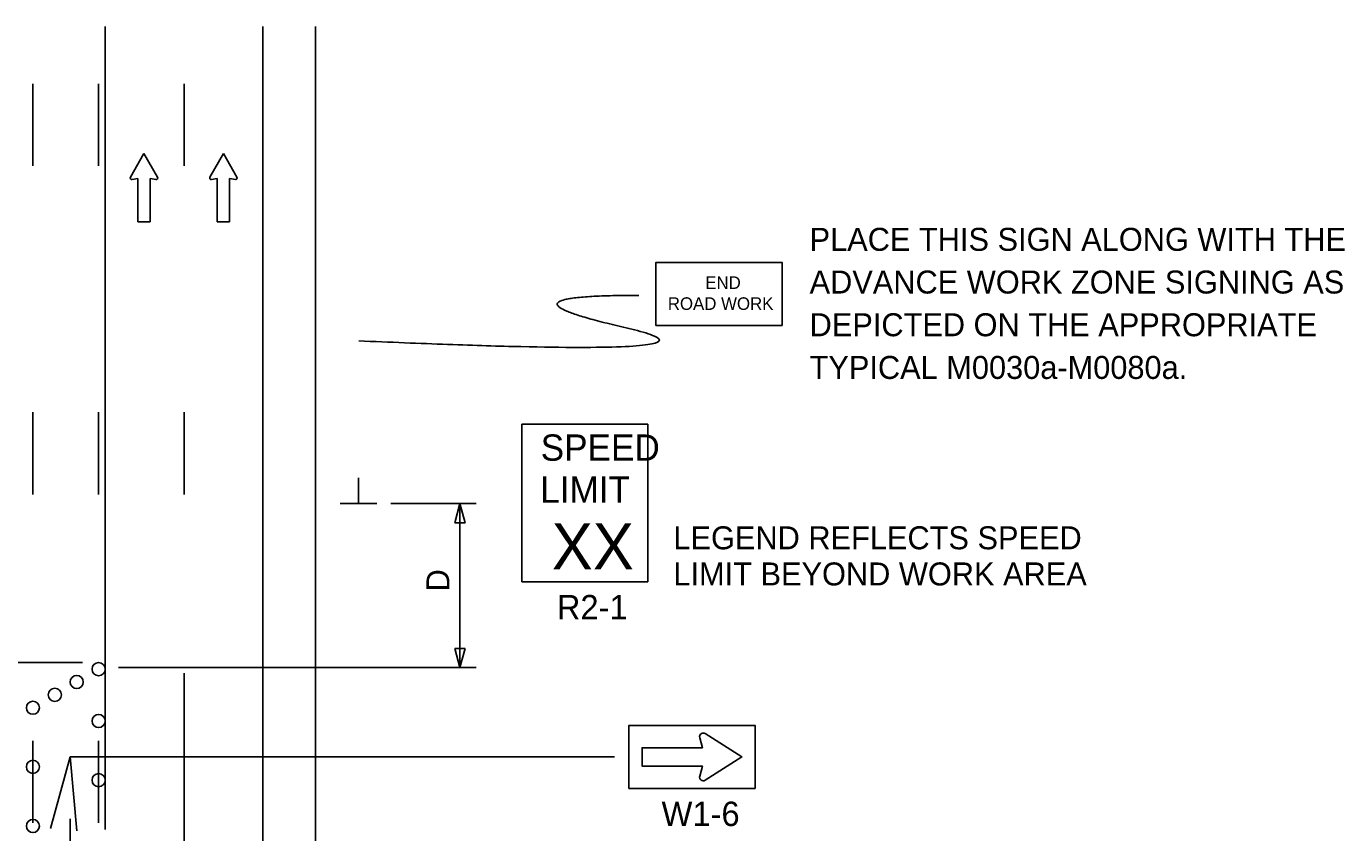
# Model space of a CAD drawing. Extents: x 16577 to 18475, y 5712 to 6919.
# Drawn here: x 16970.7 to 17372.2, y 6656 to 6901.4 of the extents above; entities that cross this region are included whole.
import ezdxf

# ---------------------------------------------------------------- set-up
doc = ezdxf.new("R2010")
doc.units = 0
for name, color, linetype in [('ALI_LEGAL_EX', 7, 'Continuous'), ('MT_SCRATCH_LEVEL_E', 7, 'Continuous'), ('PAVT_EDGE_EX', 7, 'Continuous'), ('TRAFFIC_SIGNS_PR', 7, 'Continuous'), ('TYPICAL_TEXT_DIMEN_PR', 7, 'Continuous')]:
    doc.layers.add(name, color=color, linetype=linetype)

msp = doc.modelspace()

# ---------------------------------------------------------------- linework, layer by layer
at = {"layer": 'ALI_LEGAL_EX'}
for points in [[(16972.75, 6883.94), (16972.75, 6858.94)], [(16992.75, 6883.94), (16992.75, 6858.94)], [(17018.75, 6883.94), (17018.75, 6858.94)], [(16972.75, 6783.94), (16972.75, 6758.94)], [(16992.75, 6783.94), (16992.75, 6758.94)], [(17018.75, 6783.94), (17018.75, 6758.94)], [(16972.75, 6683.94), (16972.75, 6658.94)], [(16992.75, 6683.94), (16992.75, 6658.94)], [(17018.75, 6683.94), (17018.75, 6659.28)]]:
    msp.add_lwpolyline(points, dxfattribs=at)
at = {"layer": 'MT_SCRATCH_LEVEL_E'}
for p, q in [((17006.56, 6862.73), (17002.45, 6855.49)), ((17006.56, 6862.73), (17002.45, 6855.49)), ((17010.71, 6855.49), (17006.56, 6862.73)), ((17010.71, 6855.49), (17006.56, 6862.73)), ((17030.73, 6862.73), (17026.62, 6855.49)), ((17030.73, 6862.73), (17026.62, 6855.49)), ((17034.88, 6855.49), (17030.73, 6862.73)), ((17034.88, 6855.49), (17030.73, 6862.73)), ((17002.93, 6854.81), (17004.71, 6855.12)), ((17002.93, 6854.81), (17004.71, 6855.12)), ((17004.71, 6855.12), (17004.71, 6841.87)), ((17004.71, 6855.12), (17004.71, 6841.87)), ((17008.45, 6841.87), (17008.45, 6855.12)), ((17008.45, 6855.12), (17010.23, 6854.81)), ((17008.45, 6841.87), (17008.45, 6855.12)), ((17008.45, 6855.12), (17010.23, 6854.81)), ((17027.1, 6854.81), (17028.88, 6855.12)), ((17027.1, 6854.81), (17028.88, 6855.12)), ((17028.88, 6855.12), (17028.88, 6841.87)), ((17028.88, 6855.12), (17028.88, 6841.87)), ((17032.62, 6841.87), (17032.62, 6855.12)), ((17032.62, 6855.12), (17034.4, 6854.81)), ((17032.62, 6841.87), (17032.62, 6855.12)), ((17032.62, 6855.12), (17034.4, 6854.81)), ((17004.71, 6841.87), (17008.45, 6841.87)), ((17004.71, 6841.87), (17008.45, 6841.87)), ((17028.88, 6841.87), (17032.62, 6841.87)), ((17028.88, 6841.87), (17032.62, 6841.87))]:
    msp.add_line(p, q, dxfattribs=at)
for centre, start, end in [((17002.86, 6855.27), 150.4248, 279.9638), ((17002.86, 6855.27), 150.4248, 279.9638), ((17010.3, 6855.27), 260.0362, 29.7731), ((17010.3, 6855.27), 260.0362, 29.7731), ((17027.03, 6855.27), 150.4248, 279.9638), ((17027.03, 6855.27), 150.4248, 279.9638), ((17034.47, 6855.27), 260.0362, 29.7731), ((17034.47, 6855.27), 260.0362, 29.7731)]:
    msp.add_arc(centre, 0.463, start, end, dxfattribs=at)
at = {"layer": 'PAVT_EDGE_EX'}
for p, q in [((16994.75, 6901.43), (16994.75, 6656.96)), ((17042.75, 6901.43), (17042.75, 6139.45)), ((17058.75, 6901.43), (17058.75, 6139.45)), ((17018.75, 6704.47), (17018.75, 6640.39))]:
    msp.add_line(p, q, dxfattribs=at)
at = {"layer": 'TRAFFIC_SIGNS_PR'}
for p, q in [((17121.59, 6780.32), (17159.99, 6780.32)), ((17121.59, 6732.32), (17121.59, 6780.32)), ((17159.99, 6732.32), (17159.99, 6780.32)), ((17121.59, 6732.32), (17159.99, 6732.32)), ((17176.62, 6681.81), (17175.78, 6684.87)), ((17177.46, 6686.11), (17188.62, 6679.01)), ((17158.22, 6681.81), (17176.62, 6681.81)), ((17158.22, 6681.81), (17158.22, 6676.21)), ((17176.62, 6676.21), (17158.22, 6676.21)), ((17175.78, 6673.15), (17176.62, 6676.21)), ((17188.62, 6679.01), (17177.46, 6671.91))]:
    msp.add_line(p, q, dxfattribs=at)
for points in [[(17162.45, 6810.36), (17200.85, 6810.36), (17200.85, 6829.56), (17162.45, 6829.56)], [(17154.22, 6669.41), (17192.62, 6669.41), (17192.62, 6688.61), (17154.22, 6688.61)]]:
    msp.add_lwpolyline(points, close=True, dxfattribs=at)
for points in [[(17175.78, 6684.87), (17176.62, 6681.81), (17158.22, 6681.81), (17158.22, 6676.21), (17176.62, 6676.21), (17175.78, 6673.15)], [(17177.46, 6671.91), (17188.62, 6679.01), (17177.46, 6686.11)]]:
    msp.add_lwpolyline(points, dxfattribs=at)
for centre in [(16992.75, 6705.73), (16986.08, 6701.82), (16979.42, 6697.9), (16972.75, 6693.98), (16992.75, 6689.95), (16972.75, 6675.98), (16992.75, 6671.95), (16972.75, 6657.98)]:
    msp.add_circle(centre, 2, dxfattribs=at)
for centre, start, end in [((17176.86, 6685.16), 57.5304, 195.3269), ((17176.86, 6685.16), 57.5304, 195.3269), ((17176.86, 6672.85), 164.6731, 302.4696), ((17176.86, 6672.85), 164.6731, 302.4696)]:
    msp.add_arc(centre, 1.12, start, end, dxfattribs=at)
msp.add_open_spline([(17157.27, 6819.54), (17110.03, 6819.54), (17195.05, 6800.19), (17071.96, 6805.68)], degree=2, dxfattribs=at)
at = {"layer": 'TYPICAL_TEXT_DIMEN_PR'}
for p, q in [((17071.87, 6756.19), (17071.87, 6763.98)), ((17077.5, 6756.19), (17066.25, 6756.19)), ((17107.75, 6756.19), (17081.75, 6756.19)), ((17101.18, 6750.33), (17102.75, 6756.19)), ((17102.75, 6756.19), (17104.32, 6750.33)), ((17102.75, 6756.19), (17102.75, 6706.19)), ((17102.75, 6750.33), (17101.18, 6750.33)), ((17104.32, 6750.33), (17102.75, 6750.33)), ((17102.75, 6706.19), (17101.18, 6712.05)), ((17101.18, 6712.05), (17102.75, 6712.05)), ((17102.75, 6706.19), (17101.18, 6712.05)), ((17101.18, 6712.05), (17102.75, 6712.05)), ((17102.75, 6712.05), (17104.32, 6712.05)), ((17104.32, 6712.05), (17102.75, 6706.19)), ((17102.75, 6712.05), (17104.32, 6712.05)), ((17104.32, 6712.05), (17102.75, 6706.19)), ((16987.84, 6707.73), (16857.65, 6707.73)), ((17107.75, 6706.19), (16998.81, 6706.19)), ((16978.07, 6657.21), (16984.12, 6678.99)), ((16984.12, 6678.99), (17149.87, 6678.99)), ((16984.12, 6678.99), (16986.11, 6656.47)), ((16984.12, 6652.38), (16984.12, 6660.17))]:
    msp.add_line(p, q, dxfattribs=at)

# ---------------------------------------------------------------- texts
at = {"layer": 'TRAFFIC_SIGNS_PR'}
for s, height, p in [('PLACE THIS SIGN ALONG WITH THE', 7, (17209.24, 6833.09)), ('END', 3.831, (17177.46, 6821.49)), ('ADVANCE WORK ZONE SIGNING AS', 7, (17209.24, 6820.09)), ('ROAD WORK', 3.831, (17166.06, 6815.11)), ('DEPICTED ON THE APPROPRIATE', 7, (17209.24, 6807.09)), ('TYPICAL M0030a-M0080a.', 7, (17209.24, 6794.09)), ('SPEED', 8, (17127.36, 6769.19)), ('LIMIT', 8, (17127.2, 6756.39)), ('XX', 14.031, (17130.71, 6736.08)), ('R2-1', 7.44, (17132.27, 6720.88)), ('W1-6', 7.44, (17164.16, 6657.97))]:
    msp.add_text(s, height=height, dxfattribs=at).set_placement(p)
at = {"layer": 'TYPICAL_TEXT_DIMEN_PR'}
for s, p in [('LEGEND REFLECTS SPEED', (17167.77, 6742.22)), ('LIMIT BEYOND WORK AREA', (17167.77, 6731.22))]:
    msp.add_text(s, height=7, dxfattribs=at).set_placement(p)
msp.add_text('D', height=7, rotation=90, dxfattribs=at).set_placement((17099.55, 6729.4))

doc.saveas('drawing.dxf')
